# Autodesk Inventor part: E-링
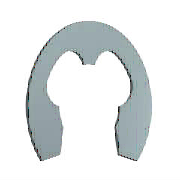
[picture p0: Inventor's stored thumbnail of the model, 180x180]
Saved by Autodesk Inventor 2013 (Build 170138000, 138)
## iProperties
IsCustomPart: 1
Created: 2012-02
Part Number: E-링
Material: 강철, 연강
Description: 리테이닝 링에 대한 사양- 탄소강 E 클립
Document SubType Name: Modeling
Standard: BS 3673-2
Designer: mduedu
Standards Organization: BSI
Language: ko-KR
Size Designation: 032MS
Categories: <MemberInstance><Categories><Category DisplayName="샤프트 부품" InternalName="7f7aeb1f-a693-4053-b835-cee3144e0d98" Mnemonic="SHFT"><Category DisplayName="써클립" Inter
Density: 1 g/cm^3
Author: mduedu
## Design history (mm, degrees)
sketch "스케치1"
  geometry: L1 (-0.4, 0.024)-(0, 0.024) reference; L2 (-3.206, 0)-(3.486, 0) reference; L3 (-1.833, -2.776)-(1.833, -2.776); L4 (0, 1.949)-(0, -3.479) reference; L5 (-2.4, -1.176)-(-2.008, -1.176); L6 (-0.4, 0.424)-(-0.4, 0.812); L7 (0, 1.524)-(2.53, 1.524); L8 (-1.833, -2.776)-(-2.096, -3.394); L9 (0, 0.024)-(-1.278, 0.024); L10 (1.833, -2.776)-(2.096, -3.394); L11 (2.4, -1.176)-(2.008, -1.176); L12 (0.4, 0.424)-(0.4, 0.812); C1 r 2 at (0, -1.976); A1 r 2 centre (0, -1.976) between (-1.894, -1.335) and (-1.833, -2.776); A2 r 0.4 centre (0, 0.424) between (-0.4, 0.424) and (0.4, 0.424); A3 r 3.5 centre (0, -1.976) between (3.196, -3.403) and (-3.196, -3.403); A4 r 3.2 centre (0, -1.976) between (-0.8, 1.122) and (-2.824, -0.47); A5 r 0.32 centre (-0.72, 0.812) between (-0.4, 0.812) and (-0.8, 1.122); A6 r 0.48 centre (-2.4, -0.696) between (-2.824, -0.47) and (-2.4, -1.176); A7 r 0.12 centre (-2.008, -1.296) between (-1.894, -1.335) and (-2.008, -1.176); A8 r 0.6 centre (-2.648, -3.158) between (-3.196, -3.403) and (-2.096, -3.394); A9 r 0.6 centre (2.648, -3.158) between (2.096, -3.394) and (3.196, -3.403); A10 r 2 centre (0, -1.976) between (1.833, -2.776) and (1.894, -1.335); A11 r 0.12 centre (2.008, -1.296) between (2.008, -1.176) and (1.894, -1.335); A12 r 0.48 centre (2.4, -0.696) between (2.4, -1.176) and (2.824, -0.47); A13 r 3.2 centre (0, -1.976) between (2.824, -0.47) and (0.8, 1.122); A14 r 0.32 centre (0.72, 0.812) between (0.8, 1.122) and (0.4, 0.812); 1 further point
  constraints: 30 point on circle, 20 end point, 15 centre point, 13 symmetric about line, 12 tangent, 8 point on line, 4 parallel, 2 coincident, 2 horizontal, 1 concentric, 1 perpendicular, 1 vertical alignment, 9 other
  dimensions: "d0" = 4 diameter of C1 (= WD); "d3" = 0.8 distance from line of A1.centre L3 (= 0.2 x ND); "d4" = 0.4 radius of A2 (= 0.1 x ND); "d5" = 7 diameter of A3 (= SD2); "d8" = 3.2 radius of A4 (= 0.8 x ND); "d9" = 0.8 distance from line of A1.centre L5 (= 0.2 x ND); "d10" = 0.32 radius of A5 (= 0.08 x ND); "d11" = 0.48 radius of A6 (= 0.12 x ND); "d12" = 0.12 radius of A7 (= 0.03 x ND); "d13" = 0.6 radius of A8 (= 0.15 x ND); "d14" = 2 distance from line of A1.centre L9 (= 0.5 x ND); "d15" = 2 radius of A1 (= 0.5 x ND)
extrude "본체" new body sketch "스케치1" distance "d16" = 0.62 (= SD); taper "d17" = 0 deg
workaxis "Work Axis1"
workaxis "Work Axis2"
workplane "Work Plane1"
body "Solid1"
other parameters: "ND" = 4 [user parameter; used in 14 equation terms], "SD" = 0.62 [user parameter; used in 1 equation term], "WD" = 4 (= WDMIN) [user parameter; used in 1 equation term], "d1" = 6.4 (= 1.6 x ND), "d2" = 4 (= ND), "SD2" = 7 [user parameter; used in 1 equation term], "d6" = 4 (= ND), "d7" = 0.6 (= 0.15 x ND), "d18" = 0, "d19" = 0, "d27" = 0, "d28" = 0, "WDMIN" = 4 [user parameter; used in 1 equation term], "SNB" = 0.67 [user parameter], "WDMAX" = 5 [user parameter], "BUBRMI" = 1 [user parameter]
